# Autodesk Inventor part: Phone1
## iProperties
Shininess: 64.0
Length Units: 11269
Angle Units: 11279
Time Units: 11290
Mass Units: 11283
Length Display Precision: 3
Angle Display Precision: 2
Compacted: True
Part Number: Phone1
Document SubType Name: Modeling
Created: 2002-12
Designer: deepak
Density: 0.0
Volumn: 0.0
Area: 0.0
PropertySet Name: Model Information
Control State: 0
Master: False
Checked Out: False
Author: deepak
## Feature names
1. Loft1
